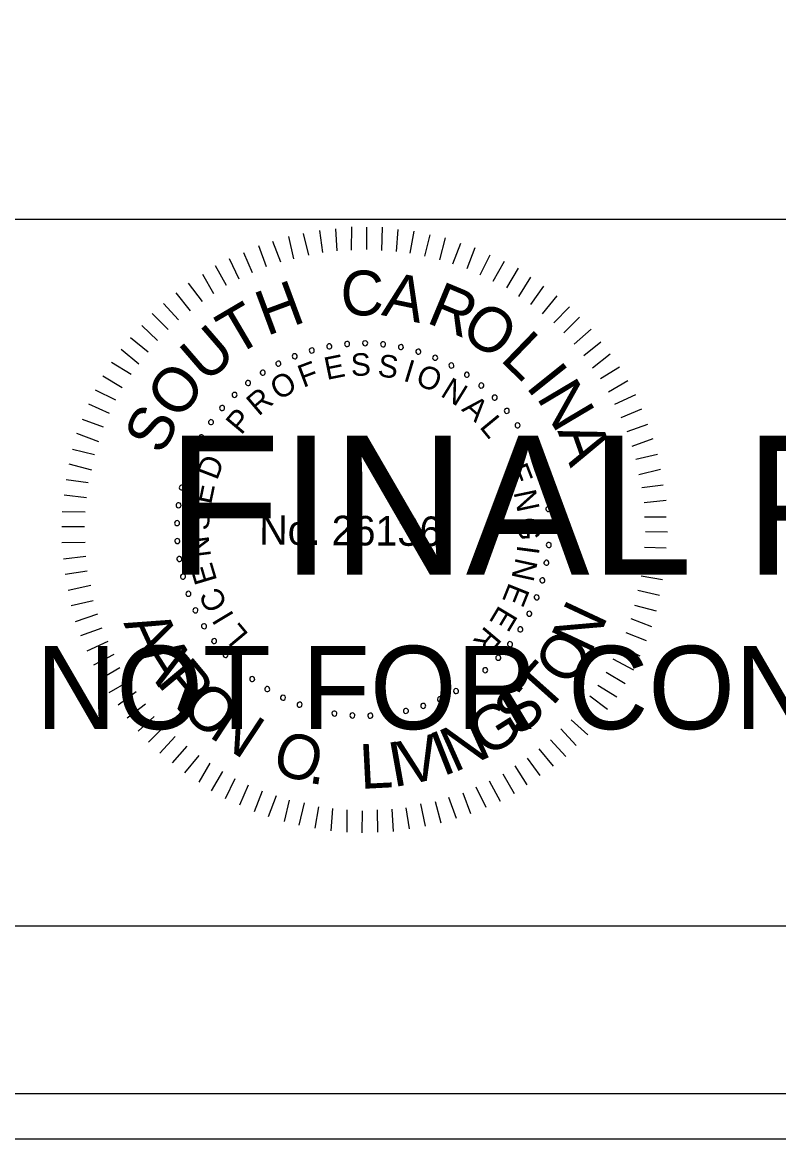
# Model space of a CAD drawing. Extents: x 967 to 1326, y 964 to 3144.
# Drawn here: x 1170.56 to 1189.3, y 2923.72 to 2951.36 of the extents above; entities that cross this region are included whole.
import ezdxf

# ---------------------------------------------------------------- set-up
doc = ezdxf.new("R2010")
doc.units = 0
for name, color, linetype in [('RD_XS_EwShp', 7, 'Continuous'), ('RD_XS_ExPaveRet', 7, 'Continuous'), ('RD_XS_TX_Elev_EX', 7, 'Continuous'), ('RD_XS_TX_Elev_PR', 7, 'Continuous'), ('RD_XS_TX_Station', 7, 'Continuous')]:
    doc.layers.add(name, color=color, linetype=linetype)

msp = doc.modelspace()

# ---------------------------------------------------------------- linework, layer by layer
at = {"layer": 'RD_XS_ExPaveRet'}
for points in [[(967.409, 2923.72), (1326.285, 2923.72), (1326.285, 3143.72), (967.409, 3143.72)], [(988.525, 2924.84), (1326.285, 2924.84), (1326.285, 3142.6), (988.525, 3142.6)]]:
    msp.add_lwpolyline(points, close=True, dxfattribs=at)
at = {"layer": 'RD_XS_TX_Elev_EX'}
for p, q in [((996.114, 2946.486), (1323.886, 2946.486)), ((1323.886, 2928.983), (996.114, 2928.983))]:
    msp.add_line(p, q, dxfattribs=at)
at = {"layer": 'RD_XS_TX_Elev_PR'}
for p, q in [((1177.657, 2945.597), (1177.53, 2946.128)), ((1178.01, 2945.663), (1177.93, 2946.209)), ((1178.364, 2945.699), (1178.33, 2946.244)), ((1178.717, 2945.719), (1178.722, 2946.295)), ((1179.093, 2945.739), (1179.098, 2946.292)), ((1179.469, 2945.713), (1179.489, 2946.288)), ((1179.829, 2945.687), (1179.872, 2946.231)), ((1180.174, 2945.646), (1180.271, 2946.19)), ((1176.964, 2945.419), (1176.769, 2945.935)), ((1177.287, 2945.508), (1177.169, 2946.054)), ((1180.535, 2945.573), (1180.662, 2946.102)), ((1180.902, 2945.478), (1181.045, 2946.022)), ((1181.231, 2945.384), (1181.428, 2945.896)), ((1176.264, 2945.156), (1176.053, 2945.657)), ((1176.61, 2945.306), (1176.423, 2945.83)), ((1181.584, 2945.265), (1181.78, 2945.786)), ((1181.905, 2945.109), (1182.154, 2945.606)), ((1175.624, 2944.846), (1175.352, 2945.332)), ((1175.933, 2945.005), (1175.699, 2945.506)), ((1182.226, 2944.953), (1182.506, 2945.45)), ((1175.308, 2944.634), (1175.036, 2945.12)), ((1182.562, 2944.789), (1182.85, 2945.27)), ((1182.86, 2944.572), (1183.163, 2945.053)), ((1175.03, 2944.445), (1174.681, 2944.9)), ((1183.158, 2944.378), (1183.484, 2944.828)), ((1174.729, 2944.217), (1174.372, 2944.665)), ((1183.447, 2944.145), (1183.811, 2944.587)), ((1174.435, 2943.997), (1174.062, 2944.399)), ((1183.729, 2943.92), (1184.116, 2944.316)), ((1174.172, 2943.753), (1173.776, 2944.148)), ((1183.98, 2943.672), (1184.368, 2944.061)), ((1173.909, 2943.479), (1173.52, 2943.858)), ((1184.232, 2943.394), (1184.657, 2943.767)), ((1173.684, 2943.197), (1173.242, 2943.546)), ((1184.475, 2943.108), (1184.892, 2943.45)), ((1173.451, 2942.9), (1173.009, 2943.256)), ((1184.687, 2942.807), (1185.128, 2943.156)), ((1173.257, 2942.64), (1172.776, 2942.936)), ((1184.885, 2942.544), (1185.355, 2942.832)), ((1173.039, 2942.312), (1172.559, 2942.6)), ((1172.883, 2942.006), (1172.379, 2942.256)), ((1185.081, 2942.213), (1185.56, 2942.493)), ((1185.24, 2941.904), (1185.756, 2942.145)), ((1172.727, 2941.677), (1172.215, 2941.904)), ((1185.399, 2941.573), (1185.907, 2941.791)), ((1172.571, 2941.333), (1172.051, 2941.53)), ((1172.461, 2940.974), (1171.91, 2941.178)), ((1185.549, 2941.226), (1186.057, 2941.414)), ((1185.669, 2940.865), (1186.185, 2941.06)), ((1172.351, 2940.652), (1171.807, 2940.787)), ((1185.759, 2940.541), (1186.297, 2940.667)), ((1172.286, 2940.276), (1171.727, 2940.419)), ((1185.832, 2940.165), (1186.371, 2940.298)), ((1172.191, 2939.955), (1171.647, 2940.029)), ((1185.906, 2939.842), (1186.436, 2939.906)), ((1172.15, 2939.587), (1171.598, 2939.653)), ((1185.964, 2939.473), (1186.51, 2939.53)), ((1172.124, 2939.234), (1171.548, 2939.239)), ((1185.977, 2939.12), (1186.514, 2939.115)), ((1172.105, 2938.866), (1171.545, 2938.871)), ((1185.997, 2938.751), (1186.542, 2938.747)), ((1172.118, 2938.482), (1171.542, 2938.471)), ((1172.138, 2938.136), (1171.585, 2938.072)), ((1185.971, 2938.368), (1186.508, 2938.348)), ((1185.952, 2938.022), (1186.497, 2937.949)), ((1172.173, 2937.768), (1171.627, 2937.688)), ((1185.888, 2937.655), (1186.417, 2937.566)), ((1172.262, 2937.414), (1171.701, 2937.296)), ((1185.808, 2937.302), (1186.345, 2937.175)), ((1172.321, 2937.037), (1171.774, 2936.911)), ((1185.729, 2936.926), (1186.265, 2936.792)), ((1172.425, 2936.707), (1171.871, 2936.519)), ((1185.634, 2936.597), (1186.146, 2936.401)), ((1172.53, 2936.36), (1172.007, 2936.173)), ((1185.508, 2936.253), (1186.013, 2936.057)), ((1172.681, 2936.029), (1172.165, 2935.788)), ((1185.352, 2935.924), (1185.857, 2935.675)), ((1172.831, 2935.705), (1172.323, 2935.441)), ((1172.982, 2935.374), (1172.497, 2935.094)), ((1185.188, 2935.603), (1185.7, 2935.33)), ((1185.024, 2935.274), (1185.498, 2934.987)), ((1173.194, 2935.042), (1172.709, 2934.762)), ((1184.822, 2934.946), (1185.288, 2934.658)), ((1173.384, 2934.78), (1172.936, 2934.453)), ((1184.62, 2934.687), (1185.055, 2934.353)), ((1173.612, 2934.478), (1173.164, 2934.129)), ((1184.403, 2934.389), (1184.814, 2934.033)), ((1173.832, 2934.177), (1173.437, 2933.812)), ((1184.155, 2934.092), (1184.574, 2933.72)), ((1174.091, 2933.945), (1173.689, 2933.541)), ((1183.899, 2933.864), (1184.28, 2933.454)), ((1174.35, 2933.674), (1173.97, 2933.263)), ((1174.64, 2933.442), (1174.275, 2933.022)), ((1183.644, 2933.597), (1184.024, 2933.18)), ((1174.937, 2933.209), (1174.58, 2932.782)), ((1183.065, 2933.141), (1183.384, 2932.709)), ((1183.358, 2933.37), (1183.715, 2932.944)), ((1175.212, 2933.014), (1174.932, 2932.549)), ((1182.764, 2932.952), (1183.059, 2932.482)), ((1175.525, 2932.812), (1175.245, 2932.331)), ((1175.83, 2932.633), (1175.588, 2932.136)), ((1182.124, 2932.581), (1182.396, 2932.08)), ((1182.463, 2932.755), (1182.743, 2932.269)), ((1176.159, 2932.477), (1175.94, 2931.98)), ((1176.503, 2932.321), (1176.307, 2931.816)), ((1181.8, 2932.431), (1182.041, 2931.93)), ((1176.855, 2932.211), (1176.651, 2931.69)), ((1177.177, 2932.1), (1177.05, 2931.572)), ((1177.545, 2932.036), (1177.409, 2931.484)), ((1180.791, 2932.07), (1180.926, 2931.54)), ((1181.122, 2932.175), (1181.31, 2931.652)), ((1181.476, 2932.28), (1181.664, 2931.771)), ((1177.897, 2931.933), (1177.808, 2931.412)), ((1178.25, 2931.892), (1178.207, 2931.34)), ((1178.603, 2931.866), (1178.598, 2931.313)), ((1178.978, 2931.84), (1178.974, 2931.295)), ((1179.355, 2931.86), (1179.365, 2931.307)), ((1179.715, 2931.88), (1179.749, 2931.327)), ((1180.061, 2931.915), (1180.149, 2931.393)), ((1180.423, 2932.012), (1180.541, 2931.458))]:
    msp.add_line(p, q, dxfattribs=at)
for centre, start, end in [((1178.168, 2943.337), 10.6038, 190.6038), ((1178.609, 2943.397), 5.0653, 185.0653), ((1178.609, 2943.397), 185.0653, 5.0653), ((1179.055, 2943.414), 359.5268, 179.5268), ((1179.055, 2943.414), 179.5268, 359.5268), ((1179.5, 2943.388), 353.9884, 173.9884), ((1179.5, 2943.388), 173.9884, 353.9884), ((1179.94, 2943.319), 348.4499, 168.4499), ((1177.312, 2943.091), 21.6807, 201.6807), ((1177.312, 2943.091), 201.6807, 21.6807), ((1177.734, 2943.235), 16.1422, 196.1422), ((1177.734, 2943.235), 196.1422, 16.1422), ((1178.168, 2943.337), 190.6038, 10.6038), ((1179.94, 2943.319), 168.4499, 348.4499), ((1180.372, 2943.208), 162.9114, 342.9114), ((1180.372, 2943.208), 342.9114, 162.9114), ((1180.79, 2943.056), 337.373, 157.373), ((1176.906, 2942.908), 27.2191, 207.2191), ((1176.906, 2942.908), 207.2191, 27.2191), ((1180.79, 2943.056), 157.373, 337.373), ((1181.193, 2942.864), 151.8345, 331.8345), ((1181.193, 2942.864), 331.8345, 151.8345), ((1176.52, 2942.686), 32.7576, 212.7576), ((1176.52, 2942.686), 212.7576, 32.7576), ((1181.574, 2942.634), 146.2961, 326.2961), ((1181.574, 2942.634), 326.2961, 146.2961), ((1176.156, 2942.428), 38.2961, 218.2961), ((1176.156, 2942.428), 218.2961, 38.2961), ((1181.932, 2942.368), 140.7576, 320.7576), ((1181.932, 2942.368), 320.7576, 140.7576), ((1175.82, 2942.135), 43.8345, 223.8345), ((1175.82, 2942.135), 223.8345, 43.8345), ((1182.263, 2942.069), 135.2191, 315.2191), ((1182.263, 2942.069), 315.2191, 135.2191), ((1175.513, 2941.812), 49.373, 229.373), ((1175.513, 2941.812), 229.373, 49.373), ((1182.563, 2941.74), 129.6807, 309.6807), ((1182.563, 2941.74), 309.6807, 129.6807), ((1175.239, 2941.461), 54.9114, 234.9114), ((1175.239, 2941.461), 234.9114, 54.9114), ((1182.83, 2941.383), 124.1422, 304.1422), ((1182.83, 2941.383), 304.1422, 124.1422), ((1175, 2941.085), 60.4499, 240.4499), ((1175, 2941.085), 240.4499, 60.4499), ((1183.061, 2941.002), 118.6038, 298.6038), ((1183.061, 2941.002), 298.6038, 118.6038), ((1174.798, 2940.687), 65.9884, 245.9884), ((1174.798, 2940.687), 245.9884, 65.9884), ((1183.255, 2940.601), 113.0653, 293.0653), ((1183.255, 2940.601), 293.0653, 113.0653), ((1174.636, 2940.272), 71.5268, 251.5268), ((1174.636, 2940.272), 251.5268, 71.5268), ((1183.408, 2940.182), 107.5268, 287.5268), ((1183.408, 2940.182), 287.5268, 107.5268), ((1174.514, 2939.843), 77.0653, 257.0653), ((1174.514, 2939.843), 257.0653, 77.0653), ((1183.521, 2939.751), 101.9884, 281.9884), ((1183.521, 2939.751), 281.9884, 101.9884), ((1174.435, 2939.405), 82.6038, 262.6038), ((1174.435, 2939.405), 262.6038, 82.6038), ((1183.592, 2939.311), 96.4499, 276.4499), ((1183.592, 2939.311), 276.4499, 96.4499), ((1174.398, 2938.961), 88.1422, 268.1422), ((1174.398, 2938.961), 268.1422, 88.1422), ((1183.619, 2938.866), 90.9114, 270.9114), ((1183.619, 2938.866), 270.9114, 90.9114), ((1174.404, 2938.515), 93.6807, 273.6807), ((1174.404, 2938.515), 273.6807, 93.6807), ((1183.604, 2938.421), 85.373, 265.373), ((1183.604, 2938.421), 265.373, 85.373), ((1174.453, 2938.072), 99.2191, 279.2191), ((1174.453, 2938.072), 279.2191, 99.2191), ((1183.546, 2937.979), 79.8345, 259.8345), ((1183.546, 2937.979), 259.8345, 79.8345), ((1174.545, 2937.636), 104.7576, 284.7576), ((1174.545, 2937.636), 284.7576, 104.7576), ((1183.445, 2937.545), 74.2961, 254.2961), ((1183.445, 2937.545), 254.2961, 74.2961), ((1174.678, 2937.211), 110.2961, 290.2961), ((1174.678, 2937.211), 290.2961, 110.2961), ((1183.303, 2937.122), 68.7576, 248.7576), ((1183.303, 2937.122), 248.7576, 68.7576), ((1174.852, 2936.8), 115.8345, 295.8345), ((1174.852, 2936.8), 295.8345, 115.8345), ((1183.121, 2936.716), 63.2191, 243.2191), ((1183.121, 2936.716), 243.2191, 63.2191), ((1175.065, 2936.409), 121.373, 301.373), ((1175.065, 2936.409), 301.373, 121.373), ((1182.9, 2936.328), 57.6807, 237.6807), ((1182.9, 2936.328), 237.6807, 57.6807), ((1175.314, 2936.039), 126.9114, 306.9114), ((1175.314, 2936.039), 306.9114, 126.9114), ((1182.643, 2935.964), 52.1422, 232.1422), ((1182.643, 2935.964), 232.1422, 52.1422), ((1175.598, 2935.696), 132.4499, 312.4499), ((1175.598, 2935.696), 312.4499, 132.4499), ((1182.353, 2935.627), 46.6038, 226.6038), ((1182.353, 2935.627), 226.6038, 46.6038), ((1175.914, 2935.381), 137.9884, 317.9884), ((1175.914, 2935.381), 317.9884, 137.9884), ((1182.03, 2935.319), 41.0653, 221.0653), ((1182.03, 2935.319), 221.0653, 41.0653), ((1176.258, 2935.099), 143.5268, 323.5268), ((1176.258, 2935.099), 323.5268, 143.5268), ((1181.68, 2935.043), 35.5268, 215.5268), ((1181.68, 2935.043), 215.5268, 35.5268), ((1176.629, 2934.851), 149.0653, 329.0653), ((1176.629, 2934.851), 329.0653, 149.0653), ((1181.305, 2934.803), 29.9884, 209.9884), ((1181.305, 2934.803), 209.9884, 29.9884), ((1177.021, 2934.639), 154.6038, 334.6038), ((1177.021, 2934.639), 334.6038, 154.6038), ((1177.432, 2934.467), 340.1422, 160.1422), ((1180.908, 2934.6), 24.4499, 204.4499), ((1180.908, 2934.6), 204.4499, 24.4499), ((1177.432, 2934.467), 160.1422, 340.1422), ((1177.858, 2934.335), 165.6807, 345.6807), ((1177.858, 2934.335), 345.6807, 165.6807), ((1178.294, 2934.245), 351.2191, 171.2191), ((1178.294, 2934.245), 171.2191, 351.2191), ((1178.737, 2934.198), 356.7576, 176.7576), ((1179.183, 2934.193), 2.2961, 182.2961), ((1179.627, 2934.232), 7.8345, 187.8345), ((1179.627, 2934.232), 187.8345, 7.8345), ((1180.065, 2934.313), 13.373, 193.373), ((1180.065, 2934.313), 193.373, 13.373), ((1180.494, 2934.436), 18.9114, 198.9114), ((1180.494, 2934.436), 198.9114, 18.9114), ((1178.737, 2934.198), 176.7576, 356.7576), ((1179.183, 2934.193), 182.2961, 2.2961)]:
    msp.add_arc(centre, 0.0627, start, end, dxfattribs=at)
at = {"layer": 'RD_XS_TX_Station'}
msp.add_lwpolyline([(967.409, 2923.72), (1326.285, 2923.72), (1326.285, 3143.72), (967.409, 3143.72)], close=True, dxfattribs=at)

# ---------------------------------------------------------------- texts
at = {"layer": 'RD_XS_EwShp'}
for s, height, p in [('FINAL PLANS', 3.4375, (1174.145, 2937.685)), ('NOT FOR CONSTRUCTION', 2.0625, (1170.901, 2933.86))]:
    msp.add_text(s, height=height, dxfattribs=at).set_placement(p)
at = {"layer": 'RD_XS_TX_Elev_PR'}
for s, height, rotation, p in [('C', 1.11, 359.5482, (1178.442, 2944.108)), ('A', 1.11, 348.1981, (1179.439, 2944.115)), ('H', 1.11, 20.3637, (1176.614, 2943.587)), ('R', 1.11, 337.4344, (1180.541, 2943.937)), ('T', 1.11, 30.4992, (1175.828, 2943.072)), ('O', 1.108, 326.5869, (1181.366, 2943.609)), ('U', 1.11, 40.8022, (1175.102, 2942.403)), ('L', 1.11, 315.9488, (1182.373, 2943.003)), ('E', 0.557, 11.4103, (1178.103, 2942.503)), ('S', 0.557, 2.208, (1178.709, 2942.601)), ('S', 0.557, 352.6608, (1179.346, 2942.599)), ('O', 1.11, 52.0267, (1174.435, 2941.474)), ('F', 0.557, 20.6127, (1177.52, 2942.309)), ('I', 0.557, 343.1136, (1179.975, 2942.491)), ('O', 0.557, 338.4392, (1180.274, 2942.401)), ('I', 1.11, 308.6613, (1183.011, 2942.338)), ('O', 0.557, 30.8477, (1176.917, 2941.987)), ('N', 0.557, 328.2042, (1180.896, 2942.12)), ('N', 1.11, 300.7037, (1183.285, 2942.075)), ('R', 0.557, 40.3949, (1176.415, 2941.594)), ('A', 0.557, 318.657, (1181.424, 2941.762)), ('S', 1.108, 63.2511, (1174.029, 2940.619)), ('P', 0.557, 49.9421, (1175.985, 2941.124)), ('L', 0.557, 309.4546, (1181.869, 2941.339)), ('A', 1.11, 289.4792, (1183.814, 2941.243)), ('D', 0.557, 69.0364, (1175.386, 2940.003)), ('E', 0.557, 291.049, (1182.53, 2940.307)), ('E', 0.557, 78.2388, (1175.238, 2939.407)), ('N', 0.557, 281.8466, (1182.728, 2939.726)), ('S', 0.557, 87.786, (1175.187, 2938.772)), ('No. 26136', 0.7311, 359.5268, (1176.429, 2938.43)), ('G', 0.557, 272.2995, (1182.833, 2939.097)), ('N', 0.557, 97.3332, (1175.242, 2938.137)), ('I', 0.557, 262.4084, (1182.83, 2938.437)), ('E', 0.557, 106.5355, (1175.394, 2937.541)), ('N', 0.557, 257.7339, (1182.789, 2938.127)), ('C', 0.557, 116.4266, (1175.661, 2936.938)), ('E', 0.557, 248.1867, (1182.628, 2937.511)), ('N', 1.105, 64.8922, (1184.632, 2935.684)), ('I', 0.557, 121.1011, (1175.823, 2936.67)), ('E', 0.557, 238.9844, (1182.378, 2936.949)), ('A', 1.105, 294.7297, (1173.062, 2936.486)), ('L', 0.557, 129.9595, (1176.187, 2936.204)), ('R', 0.557, 229.782, (1182.041, 2936.435)), ('O', 1.105, 56.2059, (1184.102, 2934.874)), ('A', 1.105, 302.2892, (1173.414, 2935.72)), ('R', 1.105, 309.8487, (1173.865, 2935.007)), ('T', 1.105, 48.2685, (1183.515, 2934.211)), ('O', 1.105, 317.7861, (1174.434, 2934.33)), ('S', 1.105, 40.3311, (1182.842, 2933.636)), ('N', 1.105, 326.4725, (1175.158, 2933.686)), ('G', 1.105, 32.0198, (1182.059, 2933.14)), ('N', 1.105, 24.0824, (1181.252, 2932.776)), ('O', 1.105, 342.3472, (1176.697, 2932.82)), ('V', 1.105, 12.7741, (1180.033, 2932.457)), ('I', 1.105, 21.4605, (1180.976, 2932.681)), ('L', 1.105, 2.9677, (1178.943, 2932.379)), ('I', 1.105, 10.1523, (1179.743, 2932.418)), ('.', 1.105, 351.0336, (1177.623, 2932.536))]:
    msp.add_text(s, height=height, rotation=rotation, dxfattribs=at).set_placement(p)

doc.saveas('drawing.dxf')
